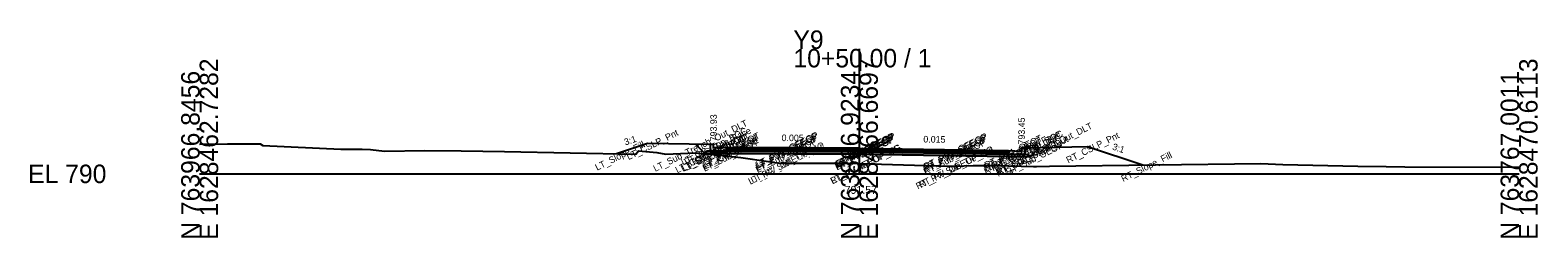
# Model space of a CAD drawing. Extents: x -26 to 203, y -10 to 6017.
# Drawn here: x -25.7 to 202.8, y 990.3 to 1021.8 of the extents above; entities that cross this region are included whole.
import ezdxf

# ---------------------------------------------------------------- set-up
doc = ezdxf.new("R2010")
doc.units = 0
for name, color, linetype in [('Default', 7, 'Continuous'), ('Exist CMT Pavement', 7, 'Continuous'), ('Exist Cross Section Cell', 7, 'Continuous'), ('Exist XS Center Line Elevation Label', 7, 'Continuous'), ('Exist XS Ground Line', 7, 'Continuous'), ('Prop CMT Conc Surface', 7, 'Continuous'), ('Prop CMT Concrete Structures', 7, 'Continuous'), ('Prop CMT Pvmt Course 1', 7, 'Continuous'), ('Prop CMT Pvmt Course 1 CG', 7, 'Continuous'), ('Prop CMT Pvmt Course 1 Wedge', 7, 'Continuous'), ('Prop CMT Pvmt Course 2', 7, 'Continuous'), ('Prop CMT Pvmt Course 2 Wedge', 7, 'Continuous'), ('Prop CMT Pvmt Course 3', 7, 'Continuous'), ('Prop CMT Pvmt Surface', 7, 'Continuous'), ('Prop CMT Pvmt Wedge Surface 1', 7, 'Continuous'), ('Prop CMT Pvmt Wedge Surface 2', 7, 'Continuous'), ('Prop CMT Pvmt Wedge Surface 3', 7, 'Continuous'), ('Prop CMT Slope Grass', 7, 'Continuous'), ('Prop CMT Subgrade Earthwork', 7, 'Continuous'), ('Prop XS Hydro Elevations', 7, 'Continuous'), ('Prop XS SE Text', 7, 'Continuous'), ('Prop XS Side Slope Text', 7, 'Continuous'), ('Scratch_Level_0', 7, 'Continuous')]:
    doc.layers.add(name, color=color, linetype=linetype)

msp = doc.modelspace()

# ---------------------------------------------------------------- linework, layer by layer
at = {"layer": 'Exist CMT Pavement'}
msp.add_lwpolyline([(113.72, 1001.15), (113.72, 1001.15)], dxfattribs=at)
at = {"layer": 'Exist Cross Section Cell'}
for p, q in [((100, 1000), (100, 1018.93)), ((0, 1000), (100, 1000)), ((100, 1000), (200, 1000))]:
    msp.add_line(p, q, dxfattribs=at)
at = {"layer": 'Exist XS Ground Line'}
msp.add_lwpolyline([(0, 1004.51), (4.21, 1004.55), (9.16, 1004.54), (9.57, 1004.28), (21.38, 1003.73), (24.61, 1003.73), (25.88, 1003.71), (28.03, 1003.46), (34.12, 1003.55), (39.66, 1003.48), (46.2, 1003.39), (66.12, 1002.99), (66.54, 1003.49), (69.32, 1003.24), (70.67, 1002.98), (72.91, 1003.08), (75.13, 1003.19), (77.78, 1002.94), (82.02, 1002.47), (86.23, 1001.87), (87.16, 1001.73), (87.98, 1001.62), (96.39, 1001.63), (97.8, 1001.63), (100, 1001.57), (108.37, 1001.32), (113.72, 1001.15), (114.4, 1001.15), (117.24, 1001.25), (120.74, 1001.25), (126.37, 1001.12), (126.84, 1001.13), (128.81, 1001.17), (160.87, 1001.57), (164.17, 1001.42), (175.56, 1001.19), (179.86, 1001.13), (182.68, 1001.07), (200, 1000.99)], dxfattribs=at)
at = {"layer": 'Prop CMT Conc Surface'}
for points in [[(77.89, 1003.93), (77.89, 1004.43), (77.39, 1004.43)], [(79.89, 1004), (77.89, 1003.93)], [(122.58, 1003.56), (124.58, 1003.45)], [(124.58, 1003.45), (124.58, 1003.95), (125.08, 1003.95)]]:
    msp.add_lwpolyline(points, dxfattribs=at)
at = {"layer": 'Prop CMT Concrete Structures'}
for points in [[(79.89, 1004), (77.89, 1003.93), (77.89, 1004.43), (77.39, 1004.43)], [(77.39, 1004.43), (77.39, 1003.43), (79.89, 1003.42)], [(79.89, 1003.42), (79.89, 1004)], [(122.58, 1003.56), (124.58, 1003.45), (124.58, 1003.95), (125.08, 1003.95)], [(125.08, 1003.95), (125.08, 1002.94), (122.58, 1002.98)], [(122.58, 1002.98), (122.58, 1003.56)]]:
    msp.add_lwpolyline(points, dxfattribs=at)
at = {"layer": 'Prop CMT Pvmt Course 1'}
for points in [[(100, 1003.9), (79.89, 1004)], [(79.89, 1004), (79.89, 1003.75)], [(79.89, 1003.75), (100, 1003.65)], [(100, 1003.65), (100, 1003.9)], [(100, 1003.9), (122.58, 1003.56)], [(100, 1003.65), (100, 1003.9)], [(100, 1003.78), (100, 1003.65), (100, 1003.65)], [(100, 1003.78), (100, 1003.65), (100, 1003.65)], [(122.58, 1003.31), (100, 1003.65)], [(122.58, 1003.56), (122.58, 1003.31)]]:
    msp.add_lwpolyline(points, dxfattribs=at)
at = {"layer": 'Prop CMT Pvmt Course 1 CG'}
for points in [[(79.89, 1003.42), (76.89, 1003.43), (76.56, 1003.1)], [(79.89, 1003.09), (79.89, 1003.42)], [(76.56, 1003.1), (79.89, 1003.09)], [(122.58, 1002.98), (125.58, 1002.93), (125.92, 1002.6)], [(122.58, 1002.65), (122.58, 1002.98)], [(125.92, 1002.6), (122.58, 1002.65)]]:
    msp.add_lwpolyline(points, dxfattribs=at)
at = {"layer": 'Prop CMT Pvmt Course 1 Wedge'}
for points in [[(100, 1003.78), (100, 1003.65)], [(100, 1003.65), (100, 1003.78)]]:
    msp.add_lwpolyline(points, dxfattribs=at)
at = {"layer": 'Prop CMT Pvmt Course 2'}
for points in [[(88.23, 1003.71), (79.89, 1003.75)], [(79.89, 1003.75), (79.89, 1003.42)], [(79.89, 1003.42), (100, 1003.32)], [(122.58, 1002.98), (100, 1003.32)], [(113.72, 1003.45), (122.58, 1003.31)], [(122.58, 1003.31), (122.58, 1002.98)]]:
    msp.add_lwpolyline(points, dxfattribs=at)
at = {"layer": 'Prop CMT Pvmt Course 2 Wedge'}
for points in [[(100, 1003.65), (100, 1003.32)], [(100, 1003.32), (100, 1003.65)]]:
    msp.add_lwpolyline(points, dxfattribs=at)
at = {"layer": 'Prop CMT Pvmt Course 3'}
for points in [[(100, 1003.32), (79.89, 1003.42)], [(79.89, 1003.42), (79.89, 1003.09)], [(100, 1003.32), (122.58, 1002.98)], [(79.89, 1003.09), (100, 1002.98)], [(122.58, 1002.65), (100, 1002.98)], [(122.58, 1002.98), (122.58, 1002.65)]]:
    msp.add_lwpolyline(points, dxfattribs=at)
at = {"layer": 'Prop CMT Pvmt Surface'}
for points in [[(100, 1003.9), (79.89, 1004)], [(100, 1003.9), (122.58, 1003.56)]]:
    msp.add_lwpolyline(points, dxfattribs=at)
at = {"layer": 'Prop CMT Pvmt Wedge Surface 1'}
for points in [[(79.89, 1003.75), (79.89, 1004)], [(100, 1003.65), (79.89, 1003.75)], [(100, 1003.65), (122.58, 1003.31)], [(122.58, 1003.31), (122.58, 1003.56)]]:
    msp.add_lwpolyline(points, dxfattribs=at)
at = {"layer": 'Prop CMT Pvmt Wedge Surface 2'}
for points in [[(79.89, 1003.75), (79.89, 1004)], [(122.58, 1003.31), (122.58, 1003.56)]]:
    msp.add_lwpolyline(points, dxfattribs=at)
at = {"layer": 'Prop CMT Pvmt Wedge Surface 3'}
for points in [[(79.89, 1003.42), (79.89, 1004)], [(122.58, 1002.98), (122.58, 1003.56)]]:
    msp.add_lwpolyline(points, dxfattribs=at)
at = {"layer": 'Prop CMT Slope Grass'}
for points in [[(77.39, 1004.43), (67.89, 1004.62), (63.17, 1003.05)], [(125.08, 1003.95), (134.58, 1004.14), (142.96, 1001.35)]]:
    msp.add_lwpolyline(points, dxfattribs=at)
at = {"layer": 'Prop CMT Subgrade Earthwork'}
for points in [[(79.89, 1003.09), (76.56, 1003.1), (75.18, 1004.48)], [(122.58, 1002.65), (125.92, 1002.6), (127.32, 1004)], [(100, 1002.98), (79.89, 1003.09)], [(100, 1002.98), (122.58, 1002.65)]]:
    msp.add_lwpolyline(points, dxfattribs=at)

# ---------------------------------------------------------------- texts
at = {"layer": 'Default'}
msp.add_text('-', height=0.0001, dxfattribs=at).set_placement((0, 1000))
at = {"layer": 'Exist Cross Section Cell'}
for s, p in [('Y9', (90, 1018.93)), ('10+50.00 / 1', (90, 1016.13)), ('EL 790', (-26, 998.6))]:
    msp.add_text(s, height=2.8, dxfattribs=at).set_placement(p)
for s, p in [('E 1628462.7282', (2.8, 990)), ('E 1628466.6697', (102.8, 990)), ('E 1628470.6113', (202.8, 990)), ('N 763966.8456', (0, 990)), ('N 763866.9234', (100, 990)), ('N 763767.0011', (200, 990))]:
    msp.add_text(s, height=2.8, rotation=90, dxfattribs=at).set_placement(p)
at = {"layer": 'Exist XS Center Line Elevation Label'}
msp.add_text('791.57', height=1.2, dxfattribs=at).set_placement((97.77, 996.97))
at = {"layer": 'Prop XS Hydro Elevations'}
for s, p in [('793.93', (78.39, 1004.93)), ('793.45', (125.08, 1004.45))]:
    msp.add_text(s, height=1, rotation=90, dxfattribs=at).set_placement(p)
at = {"layer": 'Prop XS SE Text'}
for s, rotation, p in [('0.005', 359.7135, (88.21, 1004.96)), ('0.015', 359.1406, (109.69, 1004.76))]:
    msp.add_text(s, height=1, rotation=rotation, dxfattribs=at).set_placement(p)
at = {"layer": 'Prop XS Side Slope Text'}
for rotation, p in [(18.4332, (64.54, 1004.3)), (341.5668, (138.25, 1003.71))]:
    msp.add_text('3:1', height=1, rotation=rotation, dxfattribs=at).set_placement(p)
at = {"layer": 'Scratch_Level_0'}
for s, p in [('LT_Sub_Trench_Out_DLT', (69.06, 1000.29)), ('LT_CSLP_Pnt', (65.02, 1002.07)), ('LT_CG1_Shelf_Out', (72.41, 1000.07)), ('LT_CG_Top_BOC', (73.28, 1001.26)), ('LT_CG_Bot_BOC', (73.4, 1000.32)), ('LT_CG_Top_Face', (73.79, 1001.27)), ('LT_CG_Top_Gut', (74.03, 1000.88)), ('LT_PV2_OEOT', (76.53, 1000.96)), ('LT_PV3_OEOT', (76.53, 1000.62)), ('LT_PV1_OEOT', (76.64, 1001.26)), ('LT_CG_Bot_IE', (76.69, 1000.7)), ('LT_PV2_OEEOP', (84.56, 1000.76)), ('LT_PV3_OEEOP', (84.56, 1000.42)), ('LT_PV1_OEEOP', (84.66, 1000.93)), ('RT_PV2_IEEOP', (96.61, 1000.84)), ('RT_PV3_IEEOP', (96.61, 1000.51)), ('LT_PV2_IEEOP', (96.67, 1000.87)), ('LT_PV3_IEEOP', (96.67, 1000.53)), ('RT_PV1_IEEOP', (96.72, 1001.02)), ('LT_PV1_IEEOP', (96.77, 1001.05)), ('RT_PV2_OEEOP', (109.99, 1000.46)), ('RT_PV3_OEEOP', (109.99, 1000.13)), ('RT_PV1_OEEOP', (110.1, 1000.64)), ('RT_PV2_OEOT', (119.17, 1000.49)), ('RT_PV1_OEOT', (119.27, 1000.79)), ('RT_CG_Top_Face', (120.43, 1000.76)), ('RT_CG_Top_Gut', (120.67, 1000.38)), ('RT_CG_Top_BOC', (120.92, 1000.75)), ('RT_CG1_Shelf_Out', (121.04, 999.55)), ('RT_Sub_Trench_Out_DLT', (121.14, 999.79)), ('RT_CSLP_Pnt', (131.66, 1001.57)), ('LT_Slope_Fill', (60.25, 1000.47)), ('LT_Sub_OEOP', (73.22, 1000.31)), ('LT_Sub_OEOT', (76.55, 1000.3)), ('LT_PV_Sub_Tie_Out', (83.47, 998.33)), ('LT_PV_OEEOP_EG', (83.85, 998.53)), ('LT_Sub_OEEOP', (84.58, 1000.1)), ('RT_PV_IEEOP_EG', (95.9, 998.4)), ('LT_PV_IEEOP_EG', (95.96, 998.43)), ('PV2_PGL', (98.08, 1001.57)), ('PV1_PGL', (98.18, 1001.88)), ('RT_PV_Sub_Tie_Out', (108.88, 997.62)), ('RT_PV_OEEOP_EG', (109.28, 997.81)), ('RT_Sub_OEEOP', (110.01, 999.81)), ('RT_PV3_OEOT', (119.17, 1000.16)), ('RT_Sub_OEOT', (119.19, 999.83)), ('RT_CG_Bot_IE', (119.32, 1000.23)), ('RT_CG_Bot_BOC', (121.04, 999.8)), ('RT_Sub_OEOP', (122.52, 999.78)), ('RT_Slope_Fill', (139.99, 998.75))]:
    msp.add_text(s, height=1, rotation=26.5651, dxfattribs=at).set_placement(p)

doc.saveas('drawing.dxf')
